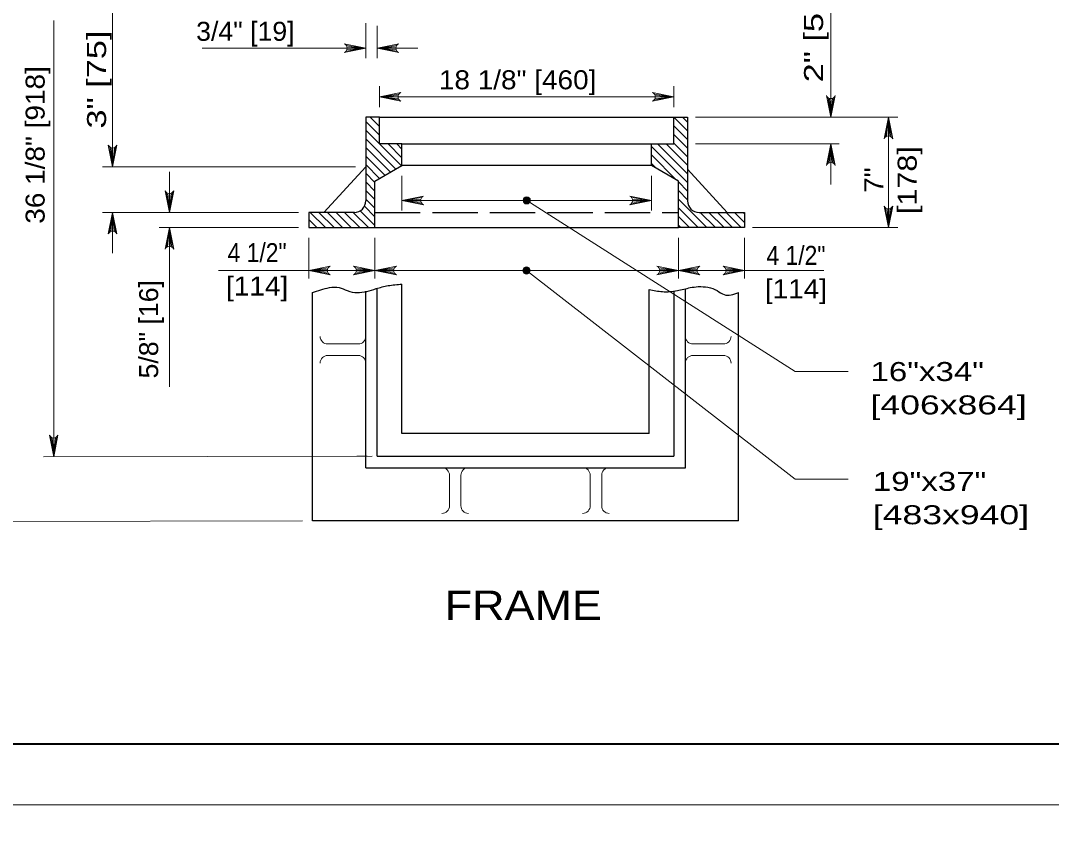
# Model space of a CAD drawing. Extents: x 1083.1 to 1117.1, y 719.4 to 763.4.
# Drawn here: x 1087.41 to 1095.88, y 741.1 to 747.79 of the extents above; entities that cross this region are included whole.
import ezdxf
from ezdxf.enums import TextEntityAlignment as Align

# ---------------------------------------------------------------- set-up
doc = ezdxf.new("R2010")
doc.units = 0
doc.header["$LTSCALE"] = 0.062
doc.linetypes.add('LONG_DASHED', pattern=[7.5, 6, -1.5])
doc.layers.add('1', color=7, linetype='Continuous', lineweight=13)

msp = doc.modelspace()

# ---------------------------------------------------------------- hatches: boundary and pattern name
at = {"layer": '1'}
for points in [[(1091.59551, 746.317, 1), (1091.53648, 746.317, 1)], [(1091.59424, 745.74162, 1), (1091.53521, 745.74162, 1)]]:
    msp.add_hatch(color=256, dxfattribs=at).paths.add_polyline_path(points)

# ---------------------------------------------------------------- linework, layer by layer
for p, q in [((1094.06467, 748.19533), (1094.06467, 746.99992)), ((1088.16492, 747.92333), (1088.16492, 746.59367)), ((1087.68067, 744.21283), (1087.68067, 747.79433)), ((1090.2445, 747.77267), (1090.2445, 747.4835)), ((1090.33825, 747.7505), (1090.33825, 747.4835)), ((1088.90042, 747.56683), (1090.2445, 747.56683)), ((1090.08225, 747.542), (1090.2445, 747.56683)), ((1090.08417, 747.58925), (1090.2445, 747.56683)), ((1090.08842, 747.55242), (1090.2445, 747.56683)), ((1090.08958, 747.57817), (1090.2445, 747.56683)), ((1090.09125, 747.56683), (1090.2445, 747.56683)), ((1090.4985, 747.58925), (1090.33825, 747.56683)), ((1090.49308, 747.57817), (1090.33825, 747.56683)), ((1090.33825, 747.56683), (1090.6715, 747.56683)), ((1090.49142, 747.56683), (1090.33825, 747.56683)), ((1090.49425, 747.55242), (1090.33825, 747.56683)), ((1090.50042, 747.542), (1090.33825, 747.56683)), ((1090.35642, 747.25542), (1090.35642, 747.08317)), ((1092.77558, 747.25542), (1092.77558, 747.08317)), ((1090.51667, 747.18892), (1090.35642, 747.1665)), ((1090.51125, 747.17783), (1090.35642, 747.1665)), ((1092.61525, 747.18892), (1092.77558, 747.1665)), ((1092.62075, 747.17783), (1092.77558, 747.1665)), ((1091.8705, 747.1665), (1090.35642, 747.1665)), ((1090.50958, 747.1665), (1090.35642, 747.1665)), ((1090.51242, 747.15208), (1090.35642, 747.1665)), ((1090.51858, 747.14175), (1090.35642, 747.1665)), ((1091.8705, 747.1665), (1092.30458, 747.1665)), ((1092.30458, 747.1665), (1092.77558, 747.1665)), ((1092.61342, 747.14175), (1092.77558, 747.1665)), ((1092.6195, 747.15208), (1092.77558, 747.1665)), ((1092.62233, 747.1665), (1092.77558, 747.1665)), ((1094.04217, 747.16017), (1094.06467, 746.99992)), ((1094.05333, 747.15475), (1094.06467, 746.99992)), ((1094.08942, 747.16208), (1094.06467, 746.99992)), ((1094.079, 747.15592), (1094.06467, 746.99992)), ((1094.06467, 747.15308), (1094.06467, 746.99992)), ((1090.35642, 746.85208), (1090.24442, 746.96408)), ((1090.35642, 746.92283), (1090.27933, 746.99992)), ((1092.88758, 746.88783), (1092.77558, 746.99983)), ((1092.88758, 746.81708), (1092.77558, 746.92908)), ((1092.88758, 746.9585), (1092.84617, 746.99992)), ((1094.6155, 746.99992), (1092.95275, 746.99992)), ((1094.512, 746.83767), (1094.53683, 746.99992)), ((1094.52242, 746.84383), (1094.53683, 746.99992)), ((1094.53683, 746.84667), (1094.53683, 746.99992)), ((1094.54817, 746.845), (1094.53683, 746.99992)), ((1094.55925, 746.83958), (1094.53683, 746.99992)), ((1094.53683, 746.99992), (1094.53683, 746.09375)), ((1090.53725, 746.60042), (1090.24442, 746.89333)), ((1092.88758, 746.74642), (1092.77558, 746.85842)), ((1088.1425, 746.754), (1088.16492, 746.59367)), ((1088.15358, 746.74858), (1088.16492, 746.59367)), ((1088.18975, 746.75592), (1088.16492, 746.59367)), ((1088.17933, 746.74975), (1088.16492, 746.59367)), ((1090.4925, 746.57458), (1090.24442, 746.82267)), ((1090.44767, 746.54867), (1090.24442, 746.75192)), ((1090.54142, 746.667), (1090.42733, 746.78117)), ((1090.54142, 746.73775), (1090.49808, 746.78117)), ((1092.88758, 746.46367), (1092.5905, 746.76067)), ((1092.88758, 746.53425), (1092.64067, 746.78117)), ((1092.88758, 746.605), (1092.71142, 746.78117)), ((1092.88758, 746.67567), (1092.77558, 746.78767)), ((1092.95275, 746.78117), (1094.13375, 746.78117)), ((1094.03983, 746.619), (1094.06467, 746.78117)), ((1094.05025, 746.62508), (1094.06467, 746.78117)), ((1094.06467, 746.62792), (1094.06467, 746.78117)), ((1094.07592, 746.62625), (1094.06467, 746.78117)), ((1094.08708, 746.62083), (1094.06467, 746.78117)), ((1094.06467, 746.78117), (1094.06467, 746.44658)), ((1088.16492, 746.74692), (1088.16492, 746.59367)), ((1090.40283, 746.52275), (1090.24442, 746.68125)), ((1092.7965, 746.48392), (1092.5905, 746.68992)), ((1088.08158, 746.59367), (1090.16108, 746.59367)), ((1090.35808, 746.49692), (1090.24442, 746.6105)), ((1092.62925, 746.5805), (1092.5905, 746.61925)), ((1088.63108, 746.55075), (1088.63108, 746.21875)), ((1090.31992, 746.46442), (1090.24442, 746.53983)), ((1090.54142, 746.5195), (1090.54142, 746.23367)), ((1092.5905, 746.5195), (1092.5905, 746.23367)), ((1090.31992, 746.39367), (1090.24442, 746.46917)), ((1092.88758, 746.39292), (1092.81208, 746.46842)), ((1088.60867, 746.37908), (1088.63108, 746.21875)), ((1088.61975, 746.37367), (1088.63108, 746.21875)), ((1088.65592, 746.38092), (1088.63108, 746.21875)), ((1088.6455, 746.37483), (1088.63108, 746.21875)), ((1088.63108, 746.372), (1088.63108, 746.21875)), ((1090.31992, 746.323), (1090.24442, 746.3985)), ((1090.31992, 746.25225), (1090.24442, 746.32775)), ((1090.70175, 746.33942), (1090.54142, 746.317)), ((1090.69633, 746.32833), (1090.54142, 746.317)), ((1092.43025, 746.33942), (1092.5905, 746.317)), ((1092.43567, 746.32833), (1092.5905, 746.317)), ((1092.88758, 746.32225), (1092.81208, 746.39775)), ((1093.04533, 746.09375), (1092.81208, 746.327)), ((1090.31992, 746.18158), (1090.233, 746.26842)), ((1090.54142, 746.317), (1092.5905, 746.317)), ((1090.69467, 746.317), (1090.54142, 746.317)), ((1090.6975, 746.30258), (1090.54142, 746.317)), ((1090.70367, 746.29217), (1090.54142, 746.317)), ((1092.42833, 746.29217), (1092.5905, 746.317)), ((1092.4345, 746.30258), (1092.5905, 746.317)), ((1092.43733, 746.317), (1092.5905, 746.317)), ((1092.97458, 746.09375), (1092.81208, 746.25625)), ((1094.51442, 746.25408), (1094.53683, 746.09375)), ((1094.5255, 746.24867), (1094.53683, 746.09375)), ((1094.56158, 746.256), (1094.53683, 746.09375)), ((1094.55125, 746.24983), (1094.53683, 746.09375)), ((1094.53683, 746.247), (1094.53683, 746.09375)), ((1089.69233, 746.21875), (1088.08158, 746.21875)), ((1088.14017, 746.05658), (1088.16492, 746.21875)), ((1088.1505, 746.06267), (1088.16492, 746.21875)), ((1088.16492, 746.0655), (1088.16492, 746.21875)), ((1088.17625, 746.06383), (1088.16492, 746.21875)), ((1088.18733, 746.05842), (1088.16492, 746.21875)), ((1088.16492, 745.88308), (1088.16492, 746.21875)), ((1089.842, 746.09375), (1089.77567, 746.16008)), ((1089.91275, 746.09375), (1089.78775, 746.21875)), ((1089.9835, 746.09375), (1089.8585, 746.21875)), ((1090.05417, 746.09375), (1089.92917, 746.21875)), ((1090.12492, 746.09375), (1089.99992, 746.21875)), ((1090.19558, 746.09375), (1090.07058, 746.21875)), ((1090.26633, 746.09375), (1090.14133, 746.21875)), ((1090.31992, 746.11083), (1090.19842, 746.23233)), ((1092.90392, 746.09375), (1092.81208, 746.18558)), ((1093.11608, 746.09375), (1092.99108, 746.21875)), ((1093.18675, 746.09375), (1093.06175, 746.21875)), ((1093.2575, 746.09375), (1093.1325, 746.21875)), ((1093.32817, 746.09375), (1093.20317, 746.21875)), ((1093.35633, 746.13633), (1093.27392, 746.21875)), ((1093.35633, 746.207), (1093.34458, 746.21875)), ((1089.69233, 746.09375), (1088.54775, 746.09375)), ((1088.60633, 745.93158), (1088.63108, 746.09375)), ((1088.61667, 745.93767), (1088.63108, 746.09375)), ((1088.63108, 744.78525), (1088.63108, 746.09375)), ((1088.63108, 745.9405), (1088.63108, 746.09375)), ((1088.64242, 745.93892), (1088.63108, 746.09375)), ((1088.6535, 745.93342), (1088.63108, 746.09375)), ((1092.83317, 746.09375), (1092.81208, 746.11483)), ((1094.6155, 746.09375), (1093.4215, 746.09375)), ((1089.77567, 745.67717), (1089.77567, 746.01042)), ((1090.31992, 745.67708), (1090.31992, 746.01033)), ((1092.81208, 745.67708), (1092.81208, 746.01033)), ((1093.35633, 745.67717), (1093.35633, 746.01042)), ((1090.9255, 745.74158), (1089.03508, 745.74158)), ((1089.936, 745.76408), (1089.77567, 745.74158)), ((1089.9305, 745.75292), (1089.77567, 745.74158)), ((1089.92892, 745.74158), (1089.77567, 745.74158)), ((1089.93175, 745.72725), (1089.77567, 745.74158)), ((1089.93783, 745.71683), (1089.77567, 745.74158)), ((1090.15767, 745.71675), (1090.31992, 745.7415)), ((1090.15958, 745.764), (1090.31992, 745.7415)), ((1090.16383, 745.72717), (1090.31992, 745.7415)), ((1090.165, 745.75283), (1090.31992, 745.7415)), ((1090.16667, 745.7415), (1090.31992, 745.7415)), ((1090.48017, 745.764), (1090.31992, 745.7415)), ((1090.47475, 745.75283), (1090.31992, 745.7415)), ((1090.47308, 745.7415), (1090.31992, 745.7415)), ((1090.47592, 745.72717), (1090.31992, 745.7415)), ((1090.48208, 745.71675), (1090.31992, 745.7415)), ((1090.9255, 745.74158), (1092.80775, 745.74158)), ((1092.64992, 745.71675), (1092.81208, 745.7415)), ((1092.65175, 745.764), (1092.81208, 745.7415)), ((1092.656, 745.72717), (1092.81208, 745.7415)), ((1092.65725, 745.75283), (1092.81208, 745.7415)), ((1092.65883, 745.7415), (1092.81208, 745.7415)), ((1092.97242, 745.764), (1092.81208, 745.7415)), ((1092.967, 745.75283), (1092.81208, 745.7415)), ((1092.81208, 745.74158), (1094.00733, 745.74158)), ((1092.96533, 745.7415), (1092.81208, 745.7415)), ((1092.96817, 745.72717), (1092.81208, 745.7415)), ((1092.97433, 745.71675), (1092.81208, 745.7415)), ((1093.19408, 745.71683), (1093.35633, 745.74167)), ((1093.196, 745.76408), (1093.35633, 745.74167)), ((1093.20025, 745.72725), (1093.35633, 745.74167)), ((1093.20142, 745.753), (1093.35633, 745.74167)), ((1093.20308, 745.74167), (1093.35633, 745.74167)), ((1090.182, 745.13817), (1089.932, 745.13817)), ((1092.93183, 745.13817), (1093.18183, 745.13817)), ((1090.182, 745.04442), (1089.932, 745.04442)), ((1092.93183, 745.04442), (1093.18183, 745.04442)), ((1087.65825, 744.37317), (1087.68067, 744.21283)), ((1087.66933, 744.36775), (1087.68067, 744.21283)), ((1087.70542, 744.37508), (1087.68067, 744.21283)), ((1087.69508, 744.36892), (1087.68067, 744.21283)), ((1087.68067, 744.36608), (1087.68067, 744.21283)), ((1087.59733, 744.21283), (1090.29658, 744.21642)), ((1090.25492, 744.21642), (1090.17158, 744.21642)), ((1090.93192, 744.06017), (1090.93192, 743.81017)), ((1091.02567, 744.06017), (1091.02567, 743.81017)), ((1092.08817, 744.06017), (1092.08817, 743.81017)), ((1092.18192, 744.06017), (1092.18192, 743.81017)), ((1087.12858, 743.68167), (1089.72367, 743.68525)), ((1089.807, 743.68525), (1093.30683, 743.68525))]:
    msp.add_line(p, q, dxfattribs=at)
at = {"layer": '1', "lineweight": 25}
for p, q in [((1090.35642, 746.99992), (1092.77567, 746.99992)), ((1090.54142, 746.78117), (1092.5905, 746.78117)), ((1090.24442, 746.59367), (1089.90067, 746.21875)), ((1092.88758, 746.57383), (1093.21317, 746.21875)), ((1090.31992, 746.09375), (1092.81208, 746.09375)), ((1090.2445, 744.12267), (1090.2445, 745.57292)), ((1090.33825, 744.21642), (1090.33825, 745.595)), ((1090.54142, 744.40392), (1090.54142, 745.62925)), ((1092.57242, 744.40392), (1092.57242, 745.58475)), ((1092.77558, 745.57208), (1092.77558, 744.21642)), ((1092.86933, 744.12267), (1092.86933, 745.59125)), ((1089.807, 743.68525), (1089.807, 745.55992)), ((1093.30683, 743.68525), (1093.30683, 745.55992)), ((1092.57242, 744.40392), (1090.54142, 744.40392)), ((1090.33825, 744.21642), (1092.77558, 744.21642)), ((1090.2445, 744.12267), (1092.86933, 744.12267)), ((1093.30683, 743.68525), (1089.807, 743.68525))]:
    msp.add_line(p, q, dxfattribs=at)
at = {"layer": '1', "linetype": 'LONG_DASHED', "lineweight": 25}
msp.add_line((1090.31992, 746.21875), (1092.81208, 746.21875), dxfattribs=at)
at = {"layer": '1', "linetype": 'LONG_DASHED'}
for points in [[(1083.12642, 741.35408), (1117.12642, 741.35408), (1117.12642, 763.35408), (1083.12642, 763.35408)], [(1083.12642, 719.35408), (1117.12642, 719.35408), (1117.12642, 741.35408), (1083.12642, 741.35408)]]:
    msp.add_lwpolyline(points, close=True, dxfattribs=at)
at = {"layer": '1', "lineweight": 25}
for points in [[(1116.62642, 741.85408), (1085.12642, 741.85408), (1085.12642, 762.85408)], [(1090.31992, 746.09375), (1090.31992, 746.47492), (1090.54142, 746.60283), (1090.54142, 746.78117), (1090.35642, 746.78117), (1090.35642, 746.99992), (1090.24442, 746.99992), (1090.24442, 746.3125)], [(1092.81208, 746.09375), (1092.81208, 746.47492), (1092.5905, 746.60283), (1092.5905, 746.78117), (1092.77558, 746.78117), (1092.77558, 746.99992), (1092.88758, 746.99992), (1092.88758, 746.3125)], [(1092.5905, 746.60283), (1092.36292, 746.60283), (1090.54142, 746.60283)], [(1090.15067, 746.21875), (1089.77567, 746.21875), (1089.77567, 746.09375), (1090.31992, 746.09375)], [(1092.98133, 746.21875), (1093.35633, 746.21875), (1093.35633, 746.09375), (1092.81208, 746.09375)]]:
    msp.add_lwpolyline(points, dxfattribs=at)
at = {"layer": '1', "lineweight": 40}
msp.add_lwpolyline([(1085.12642, 762.85408), (1116.62642, 762.85408), (1116.62642, 741.85408), (1085.12642, 741.85408)], close=True, dxfattribs=at)
msp.add_lwpolyline([(1085.12642, 762.85408), (1116.62642, 762.85408), (1116.62642, 741.85408), (1085.12642, 741.85408)], close=True, dxfattribs=at)
at = {"layer": '1'}
for points in [[(1090.06742, 747.53142), (1090.2445, 747.56683), (1090.06742, 747.60225)], [(1090.51533, 747.53142), (1090.33825, 747.56683), (1090.51533, 747.60225)], [(1090.53342, 747.13108), (1090.35642, 747.1665), (1090.53342, 747.20192)], [(1092.5985, 747.13108), (1092.77558, 747.1665), (1092.5985, 747.20192)], [(1094.1, 747.17692), (1094.06467, 746.99992), (1094.02925, 747.17692)], [(1094.50142, 746.82283), (1094.53683, 746.99992), (1094.57225, 746.82283)], [(1088.20033, 746.77075), (1088.16492, 746.59367), (1088.1295, 746.77075)], [(1094.02925, 746.60408), (1094.06467, 746.78117), (1094.1, 746.60408)], [(1088.6665, 746.39583), (1088.63108, 746.21875), (1088.59567, 746.39583)], [(1090.7185, 746.28158), (1090.54142, 746.317), (1090.7185, 746.35242)], [(1092.41342, 746.28158), (1092.5905, 746.317), (1092.41342, 746.35242)], [(1091.566, 746.317), (1093.77117, 744.91158), (1094.20625, 744.91158)], [(1094.57225, 746.27083), (1094.53683, 746.09375), (1094.50142, 746.27083)], [(1088.1295, 746.04167), (1088.16492, 746.21875), (1088.20033, 746.04167)], [(1088.59567, 745.91667), (1088.63108, 746.09375), (1088.6665, 745.91667)], [(1089.95275, 745.70617), (1089.77567, 745.74158), (1089.95275, 745.777)], [(1090.14283, 745.70608), (1090.31992, 745.7415), (1090.14283, 745.77692)], [(1090.497, 745.70608), (1090.31992, 745.7415), (1090.497, 745.77692)], [(1091.56475, 745.74158), (1093.77117, 744.02742), (1094.20625, 744.02742)], [(1092.635, 745.70608), (1092.81208, 745.7415), (1092.635, 745.77692)], [(1092.98917, 745.70608), (1092.81208, 745.7415), (1092.98917, 745.77692)], [(1093.17925, 745.70625), (1093.35633, 745.74167), (1093.17925, 745.777)], [(1087.71608, 744.38992), (1087.68067, 744.21283), (1087.64525, 744.38992)]]:
    msp.add_lwpolyline(points, dxfattribs=at)
for centre in [(1091.56599, 746.317), (1091.56472, 745.74162)]:
    msp.add_circle(centre, 0.02951, dxfattribs=at)
for centre, start, end in [((1090.0531, 747.56683), 292.08605, 67.91218), ((1090.52959, 747.56683), 112.08782, 247.91395), ((1090.54776, 747.16656), 112.08782, 247.91395), ((1092.58423, 747.16656), 292.08605, 67.91218), ((1094.06459, 747.19125), 202.08782, 337.91395), ((1094.53686, 746.8085), 22.08782, 157.91395), ((1088.1649, 746.78507), 202.08782, 337.91395), ((1094.06466, 746.58979), 22.08782, 157.91395), ((1088.63105, 746.41012), 202.08782, 337.91395), ((1090.73283, 746.31704), 112.08782, 247.91395), ((1092.39915, 746.31704), 292.08605, 67.91218), ((1094.53679, 746.28514), 202.08782, 337.91395), ((1088.16498, 746.02737), 22.08782, 157.91395), ((1088.63113, 745.90239), 22.08782, 157.91395), ((1089.96704, 745.74166), 112.08782, 247.91395), ((1090.12851, 745.74158), 292.08605, 67.91218), ((1090.51126, 745.74157), 112.08782, 247.91395), ((1092.62073, 745.74157), 292.08605, 67.91218), ((1093.00348, 745.74157), 112.08782, 247.91395), ((1093.16495, 745.74167), 292.08605, 67.91218), ((1087.68062, 744.40425), 202.08782, 337.91395)]:
    msp.add_arc(centre, 0.03822, start, end, dxfattribs=at)
at = {"layer": '1', "lineweight": 25}
for centre, start_param, end_param in [((1090.15064, 746.31248), 1.5707963, 3.1415927), ((1092.98134, 746.31248), 6.2831853, 7.8539816)]:
    msp.add_ellipse(centre, major_axis=(-0.09375, 0), ratio=0.999895, start_param=start_param, end_param=end_param, dxfattribs=at)
at = {"layer": '1'}
for centre, major_axis, start_param, end_param in [((1089.93199, 745.20065), (-0.0625, 0), 6.2831853, 7.8539816), ((1090.18197, 745.20065), (-0.0625, 0), 1.5707963, 3.1415927), ((1092.93185, 745.20065), (-0.0625, 0), 6.2831853, 7.8539816), ((1093.18183, 745.20065), (-0.0625, 0), 1.5707963, 3.1415927), ((1089.93199, 744.98194), (-0.0625, 0), 4.712389, 6.2831853), ((1090.18197, 744.98194), (0.0625, 0), 6.2831853, 7.8539816), ((1092.93185, 744.98194), (-0.0625, 0), 4.712389, 6.2831853), ((1093.18183, 744.98194), (0.0625, 0), 6.2831853, 7.8539816), ((1090.86944, 744.06016), (0.0625, 0), 6.2831853, 7.8539816), ((1091.08818, 744.06016), (0.0625, 0), 1.5707963, 3.1415927), ((1092.02564, 744.06016), (0.0625, 0), 6.2831853, 7.8539816), ((1092.24438, 744.06016), (-0.0625, 0), 4.712389, 6.2831853), ((1090.86944, 743.8102), (0.0625, 0), 4.712389, 6.2831853), ((1091.08818, 743.8102), (-0.0625, 0), 6.2831853, 7.8539816), ((1092.02564, 743.8102), (-0.0625, 0), 1.5707963, 3.1415927), ((1092.24438, 743.8102), (-0.0625, 0), 6.2831853, 7.8539816)]:
    msp.add_ellipse(centre, major_axis=major_axis, ratio=0.999895, start_param=start_param, end_param=end_param, dxfattribs=at)
at = {"layer": '1', "lineweight": 25}
for points in [[(1089.807, 745.55992), (1089.94517, 745.60075), (1090.02683, 745.60075), (1090.09217, 745.57625), (1090.17383, 745.55983), (1090.329, 745.59258), (1090.427, 745.61708), (1090.54142, 745.62925)], [(1092.57242, 745.58458), (1092.68108, 745.568), (1092.80358, 745.57625), (1092.90983, 745.60075), (1092.97517, 745.60892), (1093.13033, 745.57625), (1093.1875, 745.5435), (1093.30683, 745.55992)]]:
    msp.add_spline(points, degree=3, dxfattribs=at)

# ---------------------------------------------------------------- texts
at = {"layer": '1'}
for s, width, p in [('2" [50]', 1.35, (1094.00017, 747.28592)), ('3" [75]', 1.35, (1088.11092, 746.90683)), ('36 1/8" [918]', 1.1, (1087.6065, 746.1255)), ('5/8" [16]', 1.05, (1088.53892, 744.855))]:
    msp.add_text(s, height=0.156, rotation=90, dxfattribs=dict(at, width=width)).set_placement(p)
for s, height, width, p in [('3/4" [19]', 0.156, 1.05, (1088.851, 747.62708)), ('18 1/8" [460]', 0.156, 1.1, (1090.84483, 747.22925)), ('16"x34"', 0.156, 1.3, (1094.39025, 744.834)), ('[406x864]', 0.156, 1.4, (1094.39025, 744.55992)), ('19"x37"', 0.156, 1.3, (1094.40933, 743.93233)), ('[483x940]', 0.156, 1.4, (1094.40933, 743.65825)), ('FRAME', 0.24, 1.15, (1090.89217, 742.8735))]:
    msp.add_text(s, height=height, dxfattribs=dict(at, width=width)).set_placement(p)
for s, width, p in [('[178]', 1.2, (1094.76917, 746.4835)), ('7"', 1.1, (1094.49508, 746.48354))]:
    msp.add_text(s, height=0.156, rotation=90, dxfattribs=dict(at, width=width)).set_placement(p, align=Align.CENTER)
for s, width, p in [('4 1/2"', 0.9, (1089.35171, 745.81008)), ('4 1/2"', 0.9, (1093.77779, 745.78775)), ('[114]', 1.1, (1089.35175, 745.536)), ('[114]', 1.1, (1093.77783, 745.51367))]:
    msp.add_text(s, height=0.156, dxfattribs=dict(at, width=width)).set_placement(p, align=Align.CENTER)

doc.saveas('drawing.dxf')
